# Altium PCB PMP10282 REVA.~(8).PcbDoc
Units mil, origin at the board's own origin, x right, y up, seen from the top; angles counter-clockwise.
Board outline 3149.61 x 1181.1 mil, 2 copper layers (Top Layer, Bottom Layer), stack 62 mil thick; 58 components, 35 nets, 158 pads, 10 vias.
Unrouted connection lines stored in the file: 119.
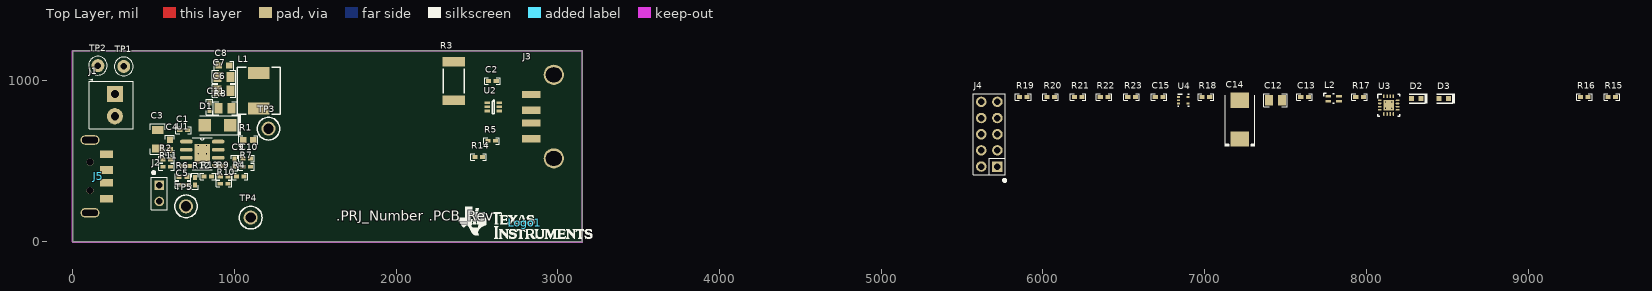
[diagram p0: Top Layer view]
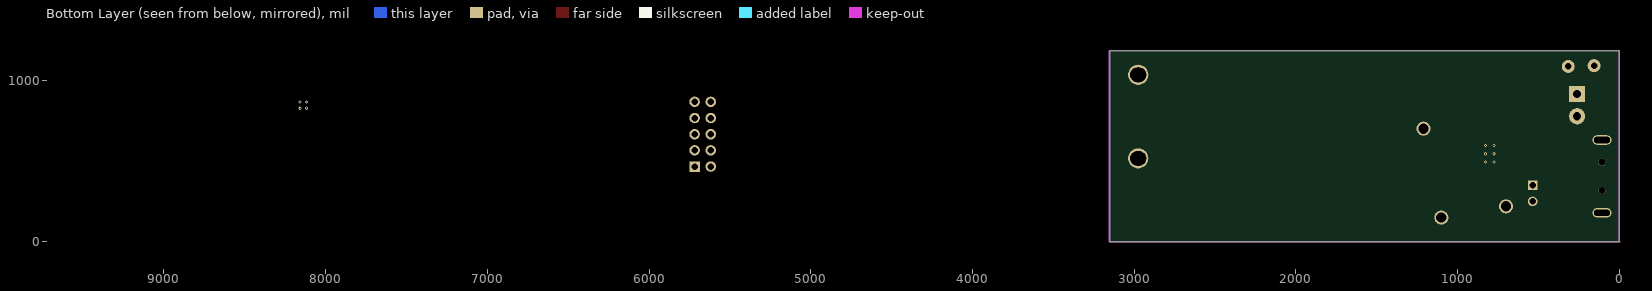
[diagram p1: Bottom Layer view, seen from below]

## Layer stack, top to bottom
Top Layer: signal copper 1.4
Dielectric: core 59.2, FR-4, Dk 4.8
Bottom Layer: signal copper 1.4

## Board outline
0,0 3149.61,0 3149.61,1181.1 0,1181.1

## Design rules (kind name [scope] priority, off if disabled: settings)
AcuteAngle [All] p1: minimum=4.50000000000000E+0001 checktracksonly=FALSE
AssemblyTestPointUsage [All] p1: valid=2
Clearance Clearance_BoardEdge_MountingHoles [OnCopper and InComponentClass('Mounting Holes') vs IsKeepOut] p1: gap=25
Clearance Clearance_BoardEdge_Poly [OnCopper and InPoly vs IsKeepOut] p2: gap=15
Clearance Clearance_BoardEdge [OnCopper and Not InComponentClass('Logo') and not InComponentClass('FiducialMark') and not InRegion(1000,500,4000,800) and Not IsKeepout vs IsKeepOut] p3: gap=25
Clearance Clearance_Poly [InPolygon] p4: gap=15
Clearance [All] p5: gap=8
ComponentClearance ComponentClearance_Shunt [InComponentClass('Header') vs InComponentClass('Shunt')] p1: gap=0 collisioncheckmode=3 verticalgap=0 showdistances=FALSE
ComponentClearance ComponentClearance_Logo [InComponentClass('Logo')] p2: gap=25 collisioncheckmode=3 verticalgap=10 showdistances=FALSE
ComponentClearance ComponentClearance_ScrewToNut [(HasFootprint('NY PMS 440 0025 PH')) vs (HasFootprint('Keystone_1902C'))] p3: gap=5 collisioncheckmode=3 verticalgap=10 showdistances=FALSE
ComponentClearance ComponentClearance_MountingHoles [InComponentClass('Mounting Holes')] p4: gap=250 collisioncheckmode=3 verticalgap=100000 showdistances=FALSE
ComponentClearance ComponentClearance_SmallPassives [HasFootprint('0201*') or HasFootprint('0402*') or HasFootprint('0508') or HasFootprint('0603*') or HasFootprint('0612') or HasFootprint('0805*') or HasFootprint('0815*') or HasFootprint('0830*') or HasFootprint('1206*') or HasFootprint('1210*') or HasFootprint('1808*') or HasFootprint('1812*') or HasFootprint('1825*') or HasFootprint('2010*') or HasFootprint('2220*') or HasFootprint('2225*') or HasFootprint('2512*') or HasFootprint('2728*') or HasFootprint('3518*') vs HasFootprint('0201*') or HasFootprint('0402*') or HasFootprint('0508') or HasFootprint('0603*') or HasFootprint('0612') or HasFootprint('0805*') or HasFootprint('0815*') or HasFootprint('0830*') or HasFootprint('1206*') or HasFootprint('1210*') or HasFootprint('1808*') or HasFootprint('1812*') or HasFootprint('1825*') or HasFootprint('2010*') or HasFootprint('2220*') or HasFootprint('2225*') or HasFootprint('2512*') or HasFootprint('2728*') or HasFootprint('3518*')] p5: gap=20 collisioncheckmode=3 verticalgap=10 showdistances=FALSE
ComponentClearance ComponentClearance_THtoSMT [IsThruComponent vs IsSMTComponent] p6: gap=25 collisioncheckmode=3 verticalgap=30 showdistances=FALSE
ComponentClearance ComponentClearance_THtoTH [IsThruComponent vs IsThruComponent] p7: gap=50 collisioncheckmode=3 verticalgap=30 showdistances=FALSE
ComponentClearance [All] p8: gap=20 collisioncheckmode=3 verticalgap=10 showdistances=FALSE
DiffPairsRouting [All] p1: maxlimit=100 minlimit=10 mostfreqgap=10 maxuncoupledlength=1000
FabricationTestPointUsage TestPointUsage [All] p1: valid=2 allowmultiple=FALSE
FabricationTestpoint Testpoint [All] p1: side=3 testpointundercomponent=TRUE minsize=40 maxsize=100 preferedsize=60 minholesize=0 maxholesize=40 preferedholesize=32 testpointgrid=1 allowsidetop=TRUE allowsidebottom=TRUE usegrid=TRUE gridtolerance=0.01
FanoutControl Fanout_LCC [IsLCC] p1: bgadir=Out bgaviamode=Centered fanoutstyle=Auto fanoutdirection=Alternating viagrid=1 // Fanout_LCC (Default Rule)
FanoutControl Fanout_BGA [IsBGA] p2: bgadir=Out bgaviamode=Centered fanoutstyle=Auto fanoutdirection=Alternating viagrid=1 // Fanout_BGA (Default Rule)
FanoutControl Fanout_Default [All] p4: bgadir=Out bgaviamode=Centered fanoutstyle=Auto fanoutdirection=Alternating viagrid=1 // Fanout_Default (Default Rule)
FanoutControl Fanout_Small [(CompPinCount < 5)] p5: bgadir=Out bgaviamode=Centered fanoutstyle=Auto fanoutdirection=OutThenIn viagrid=1 // Fanout_Small (Default Rule)
HoleSize [All] p1: absolutevalues=TRUE maxlimit=251 minlimit=8 maxpercent=80.000 minpercent=20.000
MinimumAnnularRing MinimumAnnularRing_ThermalPadVias [IsVia and InAnyComponent] p1: minimumring=5.91
MinimumAnnularRing [All] p2: minimumring=9
MinimumSolderMaskSliver MinimumSolderMaskSliver_Logo [InComponentClass('Logo') vs InComponentClass('Logo')] p1: minsoldermaskwidth=0.7
MinimumSolderMaskSliver [All] p2: minsoldermaskwidth=3
PlaneClearance [All] p1: clearance=15
PlaneConnect [All] p1: planeconnectstyle=Direct reliefexpansion=10 reliefentries=4 reliefconductorwidth=10 reliefairgap=10
PolygonConnect [All] p1: connectstyle=Direct reliefconductorwidth=10 reliefentries=4 polygonreliefangle="90 Angle" airgapwidth=10
RoutingVias ThermalPadVias [IsVia and InAnyComponent] p1: holewidth=7.87 width=19.68 viastyle="Through Hole" minholewidth=7.87 minwidth=19.68 maxholewidth=12.99 maxwidth=23.62
RoutingVias [All] p2: holewidth=16 width=34 viastyle="Through Hole" minholewidth=7.87 minwidth=26 maxholewidth=40 maxwidth=65
SMDToCorner [All] p1: distance=30000
SilkToSilkClearance [All] p1: silktosilkclearance=0
SilkscreenOverComponentPads [All] p1: minsilkscreentomaskgap=0
SolderMaskExpansion [All] p1: expansion=1.97
Width [All] p1: maxlimit=100 minlimit=6 preferedwidth=10 checkconnectedcopper=TRUE
13 further rules are at their usual default settings.

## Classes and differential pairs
component class Header: J2
component class Logo: Logo1

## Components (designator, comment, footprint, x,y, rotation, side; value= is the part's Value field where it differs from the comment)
C1 "C1005X7R1H104K050BB" 0402 685,690 r0 top
C2 "C1005X7R1H104K050BB" 0402 2595,995 r0 top
C3 "GRM31CR71H475KA12L" 1206 525,635 r90 top
C4 "UMK107AB7105KA-T" 0603 600,600 r90 top
C5 "" 0402 681.22,353.62 r0 top
C6 "GRM21BR61A226ME44" 0805_HV 935,935 r180 top
C7 "GRM21BR61A226ME44" 0805_HV 935,1020 r180 top
C8 "UMK107AB7105KA-T" 0603 935,1090 r180 top
C9 "GRM1535C1H101JDD5D" 0402 1000,488.78 r90 top
C10 "C1005C0G1E102J" 0402 1075,515 r180 top
C11 "" 0402 845,835 r270 top
C12 "GRM21BR71A106KE51L" 0805_HV 7438,876 r0 top
C13 "C1005X7R1H104K050BB" 0402 7618,896 r0 top
C14 "10TPB150ML" TPB_D4 7218,756 r90 top
C15 "C1005X7R1H104K050BB" 0402 6718,896 r0 top
D1 "B340LA-13-F" SMA 895.36,722.01 r180 top
D2 "LTST-C190GKT" LED_LTST-C190 8308,886 r0 top
D3 "LTST-C190GKT" LED_LTST-C190 8478,886 r0 top
J1 "ED555/2DS" TERM_BLK_ED555-2DS 260,915 r270 top
J2 "PEC02SAAN" CONN_PEC02SAAN 535,300 r270 top
J3 "896-43-004-00-000000" CONN_USB_896-43-004-00-000000 2905,775 r90 top
J4 "PEC05DAAN" CONN_PEC05DAAN 5668,666 r90 top
J5 "48037-1000" CONN_USB-A-48037-1000 120,405 r180 top
L1 "SPM6530T-3R3M" SPM6530 1150,935 r90 top
L2 "985DH-1026" NT2012 7798,886 r0 top
Logo1 "Texas Instruments" TI_Stacked_Overlay_Small 2795.28,118.11 r0 top
R1 "CRCW06035R11FKEA" 0603 1085,630 r0 top
R2 "CRCW0402365KFKED" 0402 580,510 r180 top
R3 "ERJ-M1WSF10MU" 2512M 2355,995 r90 top
R4 "CRCW040251R1FKED" 0402 1035,405 r0 top
R5 "CRCW040210K0FKED" 0402 2590,625 r0 top
R6 "CRCW040247K5FKED" 0402 681.22,401.81 r180 top
R7 "CRCW040224K3FKED" 0402 1075,465 r180 top
R8 "" 0805_HV 941.69,827.01 r0 top
R9 "CRCW04028K25FKED" 0402 935,405 r0 top
R10 "CRCW040213K0FKED" 0402 935,360 r180 top
R11 "CRCW040286K6FKED" 0402 580,465 r0 top
R12 "CRCW04020000Z0ED" 0402 755,375 r270 top
R13 "CRCW04021K21FKED" 0402 835,405 r0 top
R14 "CRCW040210K0FKED" 0402 2510,525 r0 top
R15 "CRCW04022K20JNED" 0402 9518,896 r0 top
R16 "CRCW04022K20JNED" 0402 9348,896 r0 top
R17 "CRCW040248K7FKED" 0402 7958,896 r0 top
R18 "CRCW040222K1FKED" 0402 7008,896 r0 top
R19 "CRCW0402100KFKED" 0402 5878,896 r0 top
R20 "CRCW0402100KFKED" 0402 6048,896 r0 top
R21 "CRCW0402100KFKED" 0402 6218,896 r0 top
R22 "CRCW0402100KFKED" 0402 6378,896 r0 top
R23 "CRCW0402100KFKED" 0402 6548,896 r0 top
TP1 "5000" Keystone5000 315,1085 r0 top
TP2 "5001" Keystone5001 155,1090 r0 top
TP3 "5010" Keystone5010 1210,700 r0 top
TP4 "5010" Keystone5010 1100,150 r0 top
TP5 "5010" Keystone5010 700,220 r0 top
U1 "TPS54340QDDAQ1" DDA0008E_N 800.59,545 r0 top
U2 "INA213AQDCKRQ1" DCK0006A_N 2600,835 r0 top
U3 "TPS2546QRTERQ1" RTE0016C 8138,846 r0 top
U4 "TPD2E001IDRLRQ1" DRL0005A 6868,876 r0 top

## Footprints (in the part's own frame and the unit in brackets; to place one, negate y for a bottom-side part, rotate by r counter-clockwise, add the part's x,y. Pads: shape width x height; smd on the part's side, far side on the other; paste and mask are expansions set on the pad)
0402 [mm] "0402 from SM-752 data"
  rect 0.8x0.6 smd: 1(-0.6,0) 2(0.6,0)
  silkscreen extent -1.22,-0.52 1.22,0.52, body extent -0.55,-0.3 0.55,0.3, height 0.6
0603 [mm] "0603 from SM-752 data"
  rect 1x0.95 smd: 1(-0.8,0) 2(0.8,0)
  silkscreen extent -1.52,-0.69 1.52,0.69, body extent -0.87,-0.47 0.87,0.47, height 0.85
0805_HV [mil] "0805 with 30mil clearance between pads"
  rect 50x63 smd: 1(-40,0) 2(40,0)
  silkscreen extent -74,-40 74,40, body extent -43,-29 43,29, height 43
1206 [mm] "1206 from SM-752 data"
  rect 1.3x1.85 smd: 1(-1.45,0) 2(1.45,0)
  silkscreen extent -2.4,-1.21 2.4,1.21, body extent -1.7,-0.9 1.7,0.9, height 1.35
2512M [mm] "Chip Resistor, Body 6.3x3.2mm, IPC Low Density"
  rect 1.5x3.5 smd: 1(-3.05,0) 2(3.05,0)
  silkscreen extent -1.9,-1.65 1.9,1.65, body extent -3.22,-1.67 3.22,1.67, height 0.71
CONN_PEC02SAAN [mm] "SULLINS"
  rect 1.5x1.5 hole 1.016: 1(-1.27,0)
  round 1.5 hole 1.016: 2(1.27,0)
  silkscreen extent -3.45,-1.27 2.54,1.27, body extent -2.54,-1.27 2.54,1.27, height 8.38
CONN_PEC05DAAN [mm] "SULLINS"
  rect 1.65x1.65 hole 1.016 mask+0: 1(-5.08,-1.27)
  round 1.65 hole 1.016 mask+0: 2(-5.08,1.27) 3(-2.54,-1.27) 4(-2.54,1.27) 5(0,-1.27) 6(0,1.27) 7(2.54,-1.27) 8(2.54,1.27) 9(5.08,-1.27) 10(5.08,1.27)
  silkscreen extent -7.45,-2.6 6.35,2.54, body extent -6.35,-2.54 6.35,2.54, height 8.38
CONN_USB-A-48037-1000 [mm] "Molex"
  rect 2x1.2 smd: 1(-2.25,3.5) 2(-2.25,1) 3(-2.25,-1) 4(-2.25,-3.5)
  round 1.092 hole 1.092 unplated: 5(0.35,2.248) 6(0.35,-2.248)
  oval 3x1.5 hole 1 slot 2.5 at 0 deg: 7(0.35,-5.715) 8(0.35,5.715)
  body extent -3.13,-6.35 18.15,6.35, height 3.09
CONN_USB_896-43-004-00-000000 [mm] "MILLMAX"
  rect 1.12x2.87 smd: 1(-3.49,1.768) 2(-1,1.768) 3(1,1.768) 4(3.49,1.768)
  round 3.17 hole 2.3 slot 2.5 at 90 deg: 5(-6.565,-1.767) 6(6.565,-1.767)
  body extent -6.55,-12.07 6.55,1.92, height 6.99
DCK0006A_N [mm] "SOT23, 6-Leads, Body 2x1.3mm, Pitch 0.65mm, Lead Span 2.1mm, IPC Medium Density"
  rect 0.85x0.4 smd: 1(-0.95,0.65) 2(-0.95,0) 3(-0.95,-0.65) 4(0.95,-0.65) 5(0.95,0) 6(0.95,0.65)
  silkscreen extent -0.15,-1.1 0.15,1.1, body extent -1.14,-1 1.14,1, height 0.94
DDA0008E_N [mm]
  oval 2x0.6 smd: 1(-2.5,1.905) 2(-2.5,0.635) 3(-2.5,-0.635) 4(-2.5,-1.905) 5(2.5,-1.905) 6(2.5,-0.635) 7(2.5,0.635) 8(2.5,1.905)
  rect 2.4x3.1 smd: 9(0,0)
  silkscreen extent -1.58,-2.49 1.58,2.49, body extent -2.98,-2.45 2.98,2.45, height 1.5
DRL0005A [mm] "SOTFL, 5-Flat Leads, Body 1.2x1.6x0.6mm, Pitch 0.5mm, TI recommended"
  rect 0.5x0.3 smd: 1(-0.75,0.5) 2(-0.75,0) 3(-0.75,-0.5) 4(0.75,-0.5) 5(0.75,0.5)
  silkscreen extent -0.9,-0.95 0.9,0.95, body extent -0.85,-0.85 0.85,0.85, height 0.62
Keystone5000 [mil] "For Keystone 500x miniature loop terminals"
  round 80 hole 40: 1(0,0)
  silkscreen extent -58,-58 58,58, body extent -49,-49 49,49, height 182
Keystone5001 [mil] "For Keystone 500x miniature loop terminals"
  round 80 hole 40: 1(0,0)
  silkscreen extent -58,-58 58,58, body extent -49,-49 49,49, height 182
Keystone5010 [mil] "Keystone Multipurpose loops"
  round 87 hole 63: 1(0,0)
  silkscreen extent -70,-70 70,70, body extent -63,-63 63,62, height 319
LED_LTST-C190 [mm] "Lite-On"
  rect 0.8x0.8 smd: 1(-0.75,0) 2(0.75,0)
  silkscreen extent -1.1,-0.8 1.8,0.8, body extent -0.85,-0.45 0.85,0.45, height 0.9
NT2012 [mm] "TOKO"
  rect 0.9x0.4 smd: 1(-0.85,0.4) 3(-0.85,-0.4) 4(0.85,-0.4) 6(0.85,0.4)
  silkscreen extent -1.55,-0.75 0.13,0.85, body extent -1.1,-0.7 1.1,0.7, height 1.31
RTE0016C [mm] "Texas Insturments"
  oval 0.6x0.24 smd paste+0: 1(-1.4,0.75) 2(-1.4,0.25) 3(-1.4,-0.25) 4(-1.4,-0.75) 9(1.4,-0.75) 10(1.4,-0.25) 11(1.4,0.25) 12(1.4,0.75)
  oval 0.24x0.6 smd paste+0: 5(-0.75,-1.4) 6(-0.25,-1.4) 7(0.25,-1.4) 8(0.75,-1.4) 13(0.75,1.4) 14(0.25,1.4) 15(-0.25,1.4) 16(-0.75,1.4)
  rect 1.66x1.66 smd paste-0.88: 17(0,0)
  silkscreen extent -1.73,-1.73 1.73,1.73, body extent -1.58,-1.58 1.58,1.58, height 0.81
SMA [mm] "Molded Diode, 2-Leads, Body 4.3x2.6mm, IPC Medium Density, based on OnSemi component dimensions and land pattern"
  rect 2x2 smd: 1(-2,0) 2(2,0)
  silkscreen extent -3.66,-1.57 2.79,1.57, body extent -2.6,-1.3 2.6,1.3, height 2.42
SPM6530 [mm] "TDK"
  rect 1.85x3.4 smd: 1(-2.775,0) 2(2.775,0)
  silkscreen extent -3.7,-3.4 3.7,3.4, body extent -3.7,-3.4 3.7,3.4, height 3.3
TERM_BLK_ED555-2DS [mil]
  rect 100x100 hole 50: 1(0,0)
  round 100 hole 50: 2(138,0)
  silkscreen extent -93,-161 215,113, body extent -69,-150 207,106, height 323
TI_Stacked_Overlay_Small [mil]
  silkscreen extent -418,-98 418,98
TPB_D4 [mm] "Panasonic recommended land pattern for size code D4"
  rect 2.4x2.9 smd: 1(-3.05,0) 2(3.05,0)
  silkscreen extent -4.25,-2.39 3.8,2.39, body extent -3.8,-2.3 3.8,2.3, height 4.01

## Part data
C1 C2 C13 C15: "CAP, CERM, 0.1uF, 50V, +/-10%, X7R, 0402"
C3: "CAP, CERM, 4.7uF, 50V, +/-10%, X7R, 1206"
C4 C8: "CAP, CERM, 1uF, 50V, +/-10%, X7R, 0603"
C5: library part C1005X7R1H104K050BB, "CAP, open, 0402"
C6 C7: "CAP, CERM, 22uF, 10V, +/-20%, X5R, 0805"
C9: "CAP, CERM, 100pF, 50V, +/-5%, C0G/NP0, 0402"
C10: "CAP, CERM, 1000pF, 25V, +/-5%, C0G/NP0, 0402"
C11: library part C1005C0G1E102J, "CAP, open, 0402"
C12: "CAP, CERM, 10uF, 10V, +/-10%, X7R, 0805"
C14: library part 10TPB220M, "CAP, 150uF, 10V, +/-20%, 0.04 ohm, SMD"
D1: "Diode, Schottky, 40V, 3A, SMA"
D2 D3: "LED, Green, SMD"
J1: "Terminal Block, 6A, 3.5mm Pitch, 2-Pos, TH"
J2: "Header, 100mil, 2x1, Tin, TH"
J3: "Connector, Receptacle, USB TYPE A, R/A, Top Mount SMT"
J4: "Header, 100mil, 5x2, Tin plated, TH"
J5: "Connector, Plug, USB Type A, R/A, Top Mount SMT"
L1: "Inductor, Shielded, Ferrite, 3.3uH, 6.8A, 0.0297 ohm, SMD"
L2: library part 985DH-1023, "Coupled inductor, 0.28A, 0.36 ohm, SMD"
Logo1: library part TI_Logo, "Texas Instrument Corporate Signature"
R1: "RES, 5.11 ohm, 1%, 0.1W, 0603"
R2: "RES, 365k ohm, 1%, 0.063W, 0402"
R3: "RES, 0.01 ohm, 1%, 1W, 2512"
R4: "RES, 51.1 ohm, 1%, 0.063W, 0402"
R5 R14: "RES, 10.0k ohm, 1%, 0.063W, 0402"
R6: "RES, 47.5k ohm, 1%, 0.063W, 0402"
R7: "RES, 24.3k ohm, 1%, 0.063W, 0402"
R8: library part CRCW08051K78FKEA, "RES, open, 0805"
R9: "RES, 8.25k ohm, 1%, 0.063W, 0402"
R10: "RES, 13.0k ohm, 1%, 0.063W, 0402"
R11: "RES, 86.6k ohm, 1%, 0.063W, 0402"
R12: "RES, 0 ohm, 5%, 0.063W, 0402"
R13: "RES, 1.21k ohm, 1%, 0.063W, 0402"
R15 R16: "RES, 2.2k ohm, 5%, 0.063W, 0402"
R17: "RES, 48.7k ohm, 1%, 0.063W, 0402"
R18: "RES, 22.1k ohm, 1%, 0.063W, 0402"
R19 R20 R21 R22 R23: "RES, 100k ohm, 1%, 0.063W, 0402"
TP1: "Test Point, TH, Miniature, Red"
TP2: "Test Point, TH, Miniature, Black"
TP3 TP4 TP5: "Test Point, Multipurpose, Red, TH"
U1: library part TPS54340DDA, "42 V Input, 3.5 A, Step Down DC-DC Converter with Eco-mode, DDA0008E"
U2: library part INA213AIDCK, "Voltage Output, High or Low Side Measurement, Bi-Directional Zero-Drift Series Current-Shunt Monitor, DCK0006A"
U3: library part TPS2546RTE, "USB Charging Port Controller and Power Switch with Load Detection, RTE0016C"
U4: "Automotive Catalog Low-Capacitance + / - 15 kV ESD-Protection Array for High-Speed Data Inter, 2 Channels, -40 to +85 degC, 5-pin SOT (DRL), Green (RoHS & no Sb/Br)"

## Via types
v1: diameter 19.68, hole 7.87, Top Layer to Bottom Layer, tented top, 6 vias
v2: diameter 19.68, hole 7.87, Top Layer to Bottom Layer, 4 vias

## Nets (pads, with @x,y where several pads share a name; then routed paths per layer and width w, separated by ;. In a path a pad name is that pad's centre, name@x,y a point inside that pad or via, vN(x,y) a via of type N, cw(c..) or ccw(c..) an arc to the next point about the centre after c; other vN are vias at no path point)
GND: C2.2 C3.2 C4.2 C6.2 C7.2 C8.2 C9.2 C10.2 C11.2 C12.2 C13.2 C14.2 C15.2 D1.2 J1.2 J2.2 J3.4 J3.5 J3.6 J4.2 J4.4 J4.6 J4.8 J4.10 J5.4 J5.7 J5.8 R11.1 R12.1 R13.1 R14.1 R17.1 R18.1 TP2.1 U1.7 U1.9 U2.2 U3.14 U3.17 U4.4
  other v1: 775,493.82 826.18,493.82 775,545 826.18,545 775,596.18 826.18,596.18
  other v2: 8118.31,826.32 8157.68,826.32 8118.31,865.68 8157.68,865.68
NetC1_1: C1.1 R1.2
NetC1_2: C1.2 U1.1
NetC2_1: C2.1 C6.1 C7.1 C8.1 L1.2 R3.1 R4.2 R5.2 U2.3 U2.5
NetC3_1: C3.1 C4.1 J1.1 R2.2 TP1.1 U1.2
NetC5_1: C5.1 R6.2 U1.4
NetC5_2: C5.2 R6.1 R12.2 TP5.1
NetC9_1: C9.1 R7.2 U1.6
NetC10_1: C10.1 R7.1
NetC11_1: C11.1 R8.1
NetC12_1: C12.1 C13.1 R3.2 R15.2 R16.2 R19.2 R20.2 R21.2 R22.2 R23.2 U2.4 U3.1
NetC14_1: C14.1 C15.1 J3.1 U3.12 U4.1
NetD1_1: D1.1 L1.1 R1.1 R8.2 TP3.1 U1.8
NetD2_1: D2.1 R16.1
NetD2_2: D2.2 U3.13
NetD3_1: D3.1 R15.1
NetD3_2: D3.2 U3.9
NetJ2_1: J2.1 R2.1 R11.2 U1.3
NetJ3_2: J3.2 L2.6 U4.5
NetJ3_3: J3.3 L2.4 U4.3
NetJ4_1: J4.1 R23.1 U3.6
NetJ4_3: J4.3 R22.1 U3.7
NetJ4_5: J4.5 R21.1 U3.8
NetJ4_7: J4.7 R20.1 U3.4
NetJ4_9: J4.9 R19.1 U3.5
NetJ5_2: J5.2 U3.2
NetJ5_3: J5.3 U3.3
NetL2_1: L2.1 U3.11
NetL2_3: L2.3 U3.10
NetR4_1: R4.1 R9.2 TP4.1
NetR5_1: R5.1 R14.2 U2.1
NetR9_1: R9.1 R10.2 R13.2 U1.5
NetR10_1: R10.1 U2.6
NetR17_2: R17.2 U3.15
NetR18_2: R18.2 U3.16
pads on no net: J5.1 J5.5 J5.6 U4.2

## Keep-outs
Keep-Out Layer:
  lines w5: -2.5,0 ccw(c0,0) 0,-2.5 ; -2.5,0 ccw(c0,0) 0,-2.5 ; -2.5,0 -2.5,1181.1 ; -2.5,1181.1 cw(c0,1181.1) 0,1183.6 ; -2.5,1181.1 cw(c0,1181.1) 0,1183.6 ; 0,-2.5 3149.61,-2.5 ; 0,1183.6 3149.61,1183.6 ; 3149.61,-2.5 ccw(c3149.61,0) 3152.11,0 ; 3149.61,-2.5 ccw(c3149.61,0) 3152.11,0 ; 3149.61,1183.6 cw(c3149.61,1181.1) 3152.11,1181.1 ; 3149.61,1183.6 cw(c3149.61,1181.1) 3152.11,1181.1 ; 3152.11,0 3152.11,1181.1
  lines w7.01: 0,0 0,1181.1 3149.61,1181.1 3149.61,0 0,0
  text ".Layer_Name" at 577,-858.49 h60

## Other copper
Top Layer:
  text ".Layer_Name" at 577,-858.49 h60
Bottom Layer:
  text ".Layer_Name" at 577,-858.49 h60

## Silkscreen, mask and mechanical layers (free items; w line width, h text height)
Top Overlay:
  text ".PRJ_Number" at 1630,130 h60
  text ".PCB_Rev" at 2200,130.01 h60
  text ".Layer_Name" at 577,-858.49 h60
Bottom Overlay:
  text ".Layer_Name" at 577,-858.49 h60
Top Paste:
  text ".Layer_Name" at 577,-858.49 h60
Bottom Paste:
  text ".Layer_Name" at 577,-858.49 h60
Top Solder:
  text ".Layer_Name" at 577,-858.49 h60
  text ".Layer_Name" at 577,-858.49 h60
Bottom Solder:
  text ".Layer_Name" at 577,-858.49 h60
Drill Guide:
  text ".Layer_Name" at 577,-858.49 h60
M1 Board Outline:
  the board outline again, w7.01
  text ".Layer_Name" at 577,-858.49 h60
M2 Board Dimensions:
  rectangle: 124.5,-410.5 499.5,-285.5
  rectangle: -0.5,-285.5 124.5,-160.5
  lines w7: -0.5,-285.5 999.5,-285.5 ; 124.5,-410.5 124.5,-160.5 ; 249.5,-410.5 249.5,-160.5 ; 499.5,-410.5 499.5,-160.5 ; 749.5,-410.5 749.5,-160.5 ; -0.5,-410.5 -0.5,-160.5 999.5,-160.5 999.5,-410.5 -0.5,-410.5
  lines w10: -0.5,-475.5 -0.5,-455.5 ; 59.5,-485.5 -0.5,-465.5 ; 59.5,-445.5 -0.5,-465.5 ; 223.58,-465.5 -0.5,-465.5 ; 775.42,-465.5 999.5,-465.5 ; 939.5,-485.5 999.5,-465.5 ; 939.5,-445.5 999.5,-465.5 ; 999.5,-475.5 999.5,-455.5
  text "1000 (mil)" at 233.58,-501.49 h60
  text ".Layer_Name" at 577,-858.49 h60
M3 3D STEP Top:
  text ".Layer_Name" at 577,-858.49 h60
M4 3D STEP Bottom:
  text ".Layer_Name" at 577,-858.49 h60
M5 Assembly Top:
  lines w10: -292,-930.17 6308,-930.17 ; -292,-726.83 6310,-726.83 ; -292,-523.5 -292,-1133.5 3713,-1133.5 6310,-1133.5 6310,-523.5 -291.5,-523.5 -291.5,-1133.5 1284,-1133.5 ; 2173,-1133.5 2173,-523.5 ; 3440,-726.83 3440,-523.5 ; 4280,-726.83 4280,-523.5 ; 4902,-1140 4902,-937.17
  text "COMPONENTS MARKED 'DNP' SHOULD NOT BE POPULATED." at 1153.5,-318.5 h60
  text "ASSEMBLY VARIANT:" at 1153,-434 h60
  text ".VariantName" at 2189,-434 h60
  text "PCB VIEWED FROM TOP SIDE" at -228.5,-655.67 h60
  text "BOARD #:" at 2248,-655.67 h60
  text ".PRJ_Number" at 2793.5,-655.67 h60
  text "REV:" at 3638,-655.67 h60
  text ".PCB_Rev" at 3929.5,-655.67 h60
  text "SVN REV:" at 4476,-655.67 h60
  text ".VersionControl_RevNumber" at 4982,-655.67 h60
  text "IGNORE ->" at -228.5,-858.49 h60
  text "PLOT NAME =" at -228.5,-1064.34 h60
  text ".plot_File_Name" at 577,-1064.34 h60
  text "GENERATED    :" at 2250,-1064.34 h60
  text ".Print_Date" at 3119.5,-1064.34 h60
  text ".Print_Time" at 3848.5,-1064.34 h60
  text "TEXAS INSTRUMENTS" at 5113,-1064.34 h60
M6 Assembly Bottom:
  lines w10: -292.5,-727.33 6309.5,-727.33 ; -290.5,-930.67 6309.5,-930.67 ; 1115.5,-1140.5 1115.5,-937.67 ; 1737.5,-727.33 1737.5,-524 ; 2577.5,-727.33 2577.5,-524 ; 3844.5,-1134 3844.5,-524 ; 4733.5,-1134 6309,-1134 6309,-524 -292.5,-524 -292.5,-1134 2304.5,-1134 6309.5,-1134 6309.5,-524
  text "COMPONENTS MARKED 'DNP' SHOULD NOT BE POPULATED." at 6102,-318 h60
  text ".VariantName" at 5058,-434 h60
  text "ASSEMBLY VARIANT:" at 6097,-434 h60
  text ".VersionControl_RevNumber" at 1035.5,-656.17 h60
  text "SVN REV:" at 1541.5,-656.17 h60
  text ".PCB_Rev" at 2088,-656.17 h60
  text "REV:" at 2379.5,-656.17 h60
  text ".PRJ_Number" at 3224,-656.17 h60
  text "BOARD #:" at 3769.5,-656.17 h60
  text "PCB VIEWED FROM BOTTOM SIDE" at 6246,-656.17 h60
  text "IGNORE ->" at 2547.85,-858.49 h60
  text "TEXAS INSTRUMENTS" at 904.5,-1064.84 h60
  text ".Print_Time" at 2169,-1064.84 h60
  text ".Print_Date" at 2898,-1064.84 h60
  text "GENERATED    :" at 3767.5,-1064.84 h60
  text ".plot_File_Name" at 5440.5,-1064.84 h60
  text "PLOT NAME =" at 6246,-1064.84 h60
M9 Title Sheet:
  drawing of 57 lines, arcs and shapes, not listed
  text "1" at 739.84,8036.5 h70
  text "2" at 3235.5,8036.5 h70
  text "3" at 5724.84,8036.5 h70
  text "4" at 8231.51,8036.5 h70
  text "5" at 10730.5,8036.5 h70
  text "6" at 13235.5,8036.5 h70
  text "A" at -416.5,6893.5 h70
  text "A" at 14383.5,6893.5 h70
  text "B" at -416.5,4513.5 h70
  text "B" at 14383.5,4513.5 h70
  text "C" at -416.5,2138.5 h70
  text "C" at 14383.5,2138.5 h70
  text "PROJECT TITLE:" at 11343.5,277.5 h45
  text ".PRJ_Title" at 11393.5,144.17 h70
  text "DESIGNED FOR:" at 11343.5,-23.5 h45
  text ".PRJ_Customer" at 11393.5,-163.5 h70
  text "D" at -416.5,-231.5 h70
  text "D" at 14383.5,-231.5 h70
  text "FILE NAME:" at 11343.5,-323.5 h45
  text ".PCB_File_Name_No_Path" at 11393.5,-443.5 h70
  text "Texas Instruments (TI) and/or its licensors do not warrant the accuracy or completeness of this specification" at 6374,-605.34 h45
  text "ENGINEER:" at 11343.5,-613.5 h45
  text "LAYOUT BY:" at 12848.5,-613.5 h45
  text "or any information contained therein. TI and/or its licensors do not warrant that this design will meet" at 6329.01,-718 h45
  text ".PRJ_Engineer" at 11393.5,-768.49 h70
  text ".PCB_Layout" at 12899,-768.49 h70
  text "the specifications, will be suitable for your application or fit for any particular purpose, or will operate in" at 6329.01,-830.67 h45
  text ".Layer_Name" at 577,-858.49 h60
  text "ALTIUM DESIGNER VERSION:" at 12848.5,-923.5 h45
  text "an implementation. TI and/or its licensors do not warrant that the design is production worthy. You should" at 6329.01,-943.33 h45
  text "completely validate and test your design implementation to confirm the system functionality for your application." at 6374,-1056 h45
  text ".print_Scale" at 11393.5,-1056.83 h70
  text ".Application_BuildNumber" at 12899,-1056.83 h70
  text "1" at 739.84,-1263.5 h70
  text "2" at 3235.5,-1263.5 h70
  text "3" at 5724.84,-1263.5 h70
  text "4" at 8231.51,-1263.5 h70
  text "5" at 10730.5,-1263.5 h70
  text "6" at 13235.5,-1263.5 h70
M10 Fab Notes:
  drawing of 212 lines, arcs and shapes, not listed
  text "DESIGN INFORMATION" at 12381.02,6810 h60
  text "(REFER ALSO ARRAY/PANEL PROFILING INFORMATION)" at 12019.46,6648.29 h60
  text "BOARD SIZE" at 11333.46,6644 h60
  text "3450MIL" at 11795.78,6516.18 h60
  text "X" at 12301.46,6516.18 h60
  text "4950MIL" at 12532.78,6516.18 h60
  text "Number of Layers :" at 11736.46,6319 h60
  text "2" at 12831.27,6309 h60
  text "MIN. TRACK WIDTH:" at 11736.46,6180 h60
  text "8" at 12832.7,6180 h60
  text "MIL" at 12987.46,6180 h60
  text "MIN. CLEARANCE:" at 11736.46,6048 h60
  text "8" at 12832.7,6048 h60
  text "MIL" at 12987.46,6048 h60
  text "MIN. VIA PAD SIZE:" at 11736.46,5916 h60
  text "24" at 12802.71,5916 h60
  text "MIL" at 12987.46,5916 h60
  text "0.05mm (2MIL)" at 12431.46,5774.29 h60
  text "MINIMUM ANNULAR RING" at 11407.23,5770 h60
  text "EXTERNAL" at 13139.46,5770 h60
  text "PER" at 11607.23,5652 h60
  text "IPC-D-275 CLASS 2 LEVEL C" at 11827.23,5652 h60
  text "MIL, HOLES" at 13315.46,5539.71 h60
  text "+/-" at 12923,5539 h60
  text "+/-" at 13777,5539 h60
  text "REGISTRATION TOLERANCES:" at 11407.23,5534 h60
  text "METAL" at 12607,5534 h60
  text "5" at 13183.2,5534 h60
  text "3" at 14016.2,5534 h60
  text "MIL" at 14132.46,5534 h60
  text "MATERIAL:" at 11332.46,5324.54 h60
  text "FR-4 High Tg" at 12318.9,5184.21 h60
  text "FR-408" at 11753.46,5175.64 h60
  text "X" at 12165.46,5175.64 h60
  text "OTHER" at 13241.46,5175.64 h60
  text "62 MIL (1.6mm) +/-10%" at 12073.56,5012.92 h60
  text "THICKNESS:" at 11407.23,5008.64 h60
  text "X" at 11945.4,5008.64 h60
  text "OTHER" at 13358.46,5008.64 h60
  text "TOLERANCE:" at 11407.23,4850.64 h60
  text "X" at 12246.53,4850.64 h60
  text "ANSI IPC-6012 TYPE 3 CLASS 2" at 12433.48,4850.64 h60
  text "OTHER +/-" at 12433.46,4694.64 h60
  text "BOW & TWIST:" at 11407.23,4537.64 h60
  text "X" at 12246.53,4537.64 h60
  text "ANSI IPC-6012 TYPE 3 CLASS 2" at 12433.48,4537.64 h60
  text "OTHER +/-" at 12433.46,4379.13 h60
  text "COPPER THICKNESS (FINISHED):" at 11332.46,4243.64 h60
  text "1.4MIL (1oz)" at 12212.46,4090.92 h60
  text "2MIL (1.4oz)" at 12979.46,4090.92 h60
  text "2.8MIL (2oz)" at 13706.46,4090.92 h60
  text "OUTER:" at 11689.46,4086.64 h60
  text "X" at 12084,4086 h60
  text "1.4MIL (1oz)" at 12212.46,3933.92 h60
  text "2.8MIL (2oz)" at 12979.46,3933.92 h60
  text "N/A" at 13706,3934.29 h60
  text "INNER SIGNAL:" at 11400.38,3929.64 h60
  text "X" at 12085.42,3929.64 h60
  text "DRILLING:" at 11332.46,3790.64 h60
  text "REFERENCE:" at 11407.23,3673.64 h60
  text "X" at 12055.46,3673.64 h60
  text "AS SHOWN" at 12242.46,3673.64 h60
  text "X" at 12956.46,3673.64 h60
  text "NC_DRILL FILES" at 13093.46,3673.64 h60
  text "PTH MIN COPPER THICKNESS:" at 11407.23,3515.64 h60
  text "X" at 12757.46,3515.64 h60
  text "1MIL" at 12894.46,3515.64 h60
  text "OTHER" at 13391.46,3515.64 h60
  text "BOARD FINISH:" at 11332.46,3356.64 h60
  text "SILKSCREEN:" at 11487.68,3238.64 h60
  text "X" at 12436.46,3238.64 h60
  text "TOP" at 12562.46,3238.64 h60
  text "X" at 12946.46,3238.64 h60
  text "BOTTOM" at 13073.46,3238.64 h60
  text "SILKSCREEN COLOR:" at 11487.68,3071.64 h60
  text "X" at 12435.42,3071.64 h60
  text "WHITE" at 12562.46,3071.64 h60
  text "OTHER" at 13073.46,3071.64 h60
  text "SOLDER RESIST COLOR:" at 11487.68,2901.64 h60
  text "X" at 12055.42,2742.44 h60
  text "GREEN" at 12182.46,2742.44 h60
  text "BLUE" at 12773.46,2742.44 h60
  text "OTHER" at 13311.46,2742.44 h60
  text "IMMERSION GOLD (ENIG)" at 12393.46,2553.92 h60
  text "ENEPIG" at 13731,2550.64 h60
  text "SURFACE FINISH:" at 11332.46,2549.64 h60
  text "X" at 12206.51,2549.64 h60
  text "IMM. TIN/SILVER OR EQUIV" at 11662,2392.64 h60
  text "OTHER" at 13093.46,2392.64 h60
  text "ARRAY/PANEL:" at 11332.46,2213.64 h60
  text "CUT AND TRIM PER MECH LAYER 1" at 12393.46,2209.35 h60
  text "N.C. ROUTE" at 12393.46,2057.64 h60
  text "X" at 13072.46,2057.64 h60
  text "V. SCORE" at 13259.46,2057.64 h60
  text "CERTIFICATION:" at 11332.46,1920.64 h60
  text "MATERIALS AND WORKMANSHIP FOR ALL PCBS" at 12057.46,1920.64 h60
  text "TO MEET OR EXCEED THE REQUIREMENTS OF:" at 12057.46,1822.64 h60
  text "X" at 11683.96,1686.13 h60
  text "ANSI IPC-A-600F CLASS ->" at 11822.96,1686.13 h60
  text "X" at 13462.02,1686.13 h60
  text "2" at 13580.96,1686.14 h60
  text "1" at 13265.96,1684.64 h60
  text "3" at 13934.96,1684.64 h60
  text "X" at 11686.02,1526.64 h60
  text "UL 94V-0" at 11822.96,1526.64 h60
  text "X" at 12498.02,1526.64 h60
  text "RoHS" at 12634.96,1526.64 h60
  text "OTHER" at 13279.36,1526.64 h60
  text "PER ORDER" at 13676.42,1526.64 h60
  text "ADDITIONAL REQUIREMENTS:" at 11332.46,1385.64 h60
  text "MICROSECTION:" at 11407.23,1270.64 h60
  text "YES" at 12312.96,1270.64 h60
  text "REQUIRED" at 13174.46,1114.49 h60
  text "BARE BOARD ELEC. TEST:" at 11407.23,1111.64 h60
  text "NONE" at 12712.96,1111.64 h60
  text "X" at 13047.46,1111.64 h60
  text "PER ORDER" at 13766.46,1111.64 h60
  text "MANUFACTURER'S UL:" at 11407.23,954.64 h60
  text "RAIL" at 12572.96,950.35 h60
  text "METAL" at 13064.77,950.35 h60
  text "X" at 13440,950 h60
  text "SILK" at 13576.46,950.35 h60
  text ".Layer_Name" at 577,-858.49 h60
M11 Gerber Information:
  lines w10: -292,-930.17 6308,-930.17 ; -292,-726.83 6310,-726.83 ; -292,-523.5 -292,-1133.5 3713,-1133.5 6310,-1133.5 6310,-523.5 -291.5,-523.5 -291.5,-1133.5 1284,-1133.5 ; 2173,-1133.5 2173,-523.5 ; 3440,-726.83 3440,-523.5 ; 4280,-726.83 4280,-523.5 ; 4902,-1140 4902,-937.17
  text "ALL ARTWORK VIEWED FROM TOP SIDE" at -228.5,-655.67 h60
  text "BOARD #:" at 2248,-655.67 h60
  text ".PRJ_Number" at 2793.5,-655.67 h60
  text "REV:" at 3638,-655.67 h60
  text ".PCB_Rev" at 3929.5,-655.67 h60
  text "SVN REV:" at 4476,-655.67 h60
  text ".VersionControl_RevNumber" at 4982,-655.67 h60
  text "LAYER NAME =" at -228.5,-858.49 h60
  text "PLOT NAME =" at -228.5,-1064.34 h60
  text ".plot_File_Name" at 577,-1064.34 h60
  text "GENERATED    :" at 2250,-1064.34 h60
  text ".Print_Date" at 3119.5,-1064.34 h60
  text ".Print_Time" at 3848.5,-1064.34 h60
  text "TEXAS INSTRUMENTS" at 5113,-1064.34 h60
M12 Stackup:
  lines w6: 11360,7460 13910,7460 ; 11360,7564.4 13910,7564.4 ; 11300,6975 ccw(c11334,6975) 11334,6941 13936,6941 ccw(c13936,6975) 13970,6975 13970,7681 ccw(c13936,7681) 13936,7715 11334,7715 ccw(c11334,7681) 11300,7681 11300,6975
  text "The Stackup Legend below this is static." at 11605.5,7874.5 h60
  text "If you change the stackup, update the Legend." at 11615.5,7784.5 h60
  text "Layer Stack Up Detail for: Ref_Design.PcbDoc" at 11360,7597.1 h57
  text "Layer" at 11360,7525.4 h24
  text "Gerber" at 12255.81,7525.4 h24
  text "Copper" at 12819.33,7525.4 h24
  text "Dielectric" at 13422.04,7525.4 h24
  text "Name" at 11360,7477.4 h24
  text "Document" at 12255.81,7477.4 h24
  text "Thickness" at 12819.33,7477.4 h24
  text "Material" at 13422.04,7477.4 h24
  text "Top Solder Mask" at 11360,7384.44 h34
  text "(.GTS)" at 12255.81,7384.44 h34
  text "Solder Resist" at 13422.04,7384.44 h34
  text "Top Layer" at 11360,7287.69 h34
  text "(.GTL)" at 12255.81,7287.69 h34
  text "1.4mil" at 12819.33,7287.69 h34
  text "FR-4" at 13422.04,7239.31 h34
  text "Bottom Layer" at 11360,7190.94 h34
  text "(.GBL)" at 12255.81,7190.94 h34
  text "1.4mil" at 12819.33,7190.94 h34
  text "Bottom Solder Mask" at 11360,7094.19 h34
  text "(.GBS)" at 12255.81,7094.19 h34
  text "Solder Resist" at 13422.04,7094.19 h34
  text ".Layer_Name" at 577,-858.49 h60
M13 Component Bodies Top:
  text ".Layer_Name" at 577,-858.49 h60
M14 Component Bodies Bottom:
  text ".Layer_Name" at 577,-858.49 h60
M15 Courtyards Top:
  text ".Layer_Name" at 577,-858.49 h60
M16 Courtyards Bottom:
  text ".Layer_Name" at 577,-858.49 h60
Drill Drawing:
  text ".legend" at 5122.5,725.5 h60
  text "Drill Table" at 5147.5,540.5 h60
  text ".Layer_Name" at 577,-858.49 h60

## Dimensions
0,0 to 3149.61,0 on M2 Board Dimensions
0,0 to 0,1181.1 on M2 Board Dimensions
